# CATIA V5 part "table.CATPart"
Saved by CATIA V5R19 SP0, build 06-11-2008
Part number: table
Bounding box of the stored display mesh (mm): x 0 to 300, y -120 to 120, z -25 to 10
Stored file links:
  C:\Users\Alex\IFMA\2A\IAO\Modélisation\table.CATPart
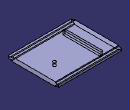
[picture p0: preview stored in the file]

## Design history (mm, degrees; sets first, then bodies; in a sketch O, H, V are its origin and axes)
Body1 (main body)
  Sketch1 on yz-plane, origin (0, 0, 0), H (0, 1, 0), V (0, 0, 1)
    line L1 (-120, 5) -> (-105, 5)
    line L2 (-105, 5) -> (-105, 10)
    line L3 (-105, 10) -> (0, 10)
    line L4 (-120, -5) -> (-120, 5)
    line L5 (0, 10) -> (0, -10)
    line L6 (0, -10) -> (-105, -10)
    point P7 (-105, -10)
    line L7 (-120, -5) -> (-105, -5)
    point P8 (-105, -5)
    line L8 (-105, -5) -> (-105, -10)
    length L4 = 10
    distance L4 L2 = 15
    length L5 = 20
    distance L5 L4 = 120
    length L2 = 5
    distance L6 H = 10
    horizontal: L1 H, L3 H, L6 H, L7 H
    vertical: L2 V, L4 V, L5 V
    coincidence: P7 L2, P8 L2, L5 V
    parallelism: L8 L2
  Pad1: profile Sketch1, direction (1, 0, 0), length 300
  Mirror1: of Pad1, about face of Pad1 from Sketch1.L5
  Sketch2 on face of Mirror1, origin (0, 0, 10), H (1, 0, 0), V (0, 1, 0)
    line L1 (60, 90) -> (70, 90)
    line L2 (70, 90) -> (70, -90)
    line L3 (70, -90) -> (60, -90)
    line L4 (60, -90) -> (60, 90)
    reference projected line E1 (0, 0) -> (0, -105) from edge [face of Mirror1 | face of Mirror1]
    length L2 = 180
    distance L1 H = 90
    distance L4 E1 = 60
    length L1 = 10
    horizontal: L1 H, L3 H
    vertical: L2 V, L4 V
  Pocket1: profile Sketch2, direction (0, 0, -1), through (limit type 3)
  Sketch3 on face of Mirror1, origin (0, 0, -10), H (1, 0, 0), V (0, -1, 0)
    circle A1 centre (200, 0) radius 7.5
    point P1 (200, 0)
    reference projected line E1 (0, 105) -> (300, 105) from edge [face of Mirror1 | face of Pad1 from Sketch1.L8]
    reference projected line E2 (300, 105) -> (300, 0) from edge [face of Mirror1 | face of Mirror1]
    distance P1 E1 = 105
    distance P1 E2 = 100
    radius A1 = 7.5
  Pad2: profile Sketch3, direction (0, 0, -1), length 15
